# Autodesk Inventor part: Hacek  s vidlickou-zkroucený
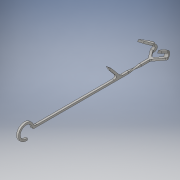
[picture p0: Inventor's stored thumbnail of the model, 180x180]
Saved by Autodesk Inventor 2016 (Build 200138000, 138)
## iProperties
Created: 2015-07
Part Number: Hacek  s vidlickou-zkroucený
Material: Generic
Document SubType Name: Modeling
Designer: brecka
Density: 1 g/cm^3
Appearance: Default
Author: brecka
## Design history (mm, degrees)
derived "Hacek  s vidlickou-vrchni  cast.ipt"
derived "Hacek  s vidlickou-spodní  část.ipt"
node "Pracovní osa1"
  node "Pracovní rovina1"
  node "Pracovní rovina2"
node "Upravit přímo1"
sketch "Náčrt1"
  geometry: L1 (0, 0)-(3, 0) reference; L2 (0, -3)-(0, 0) reference; L3 (3, -3)-(0, -3) reference; L4 (3, 0)-(3, -3) reference; 1 further point
  node "Promítnutá smyčka1"
sketch "Náčrt2"
  geometry: L1 (0, 0)-(0, 3) reference; L2 (3, 0)-(0, 0) reference; L3 (3, 3)-(3, 0) reference; L4 (0, 3)-(3, 3) reference; 1 further point
  node "Promítnutá smyčka2"
feature "Šablonování1" dims "d3" = 0, "d4" = 90 deg, "d5" = 0, "d6" = 90 deg
  node "Hrany1"
  node "Hrany2"
feature "Těleso1::Hacek  s vidlickou-vrchni  cast.ipt" dims "d0" = 10
tag "Prvek štítků1"
feature "Těleso1::Hacek  s vidlickou-spodní  část.ipt" dims "d1" = 10
tag "Prvek štítků2"
node "Těleso1"
node "Těleso2"
feature "Otočit1" dims "d2" = 90 deg
